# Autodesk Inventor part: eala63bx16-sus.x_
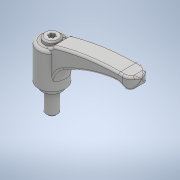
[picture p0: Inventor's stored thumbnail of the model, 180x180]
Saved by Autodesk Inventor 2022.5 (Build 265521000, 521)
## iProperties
Created: 2018-05
Part Number: eala63bx16-sus.x_
Material: 一般
Document SubType Name: Modeling
Designer: imaocorp
Density: 1 g/cm^3
Appearance: 既定
Sending System: SOLIDWORKS 2016-2016286
MC: AMD64
MC_MODEL: AMD64 Family 21 Model 2 Stepping 0, AuthenticAMD
OS: Windows_NT
FRU: Parasolid Version 28.0, build 224,  7-29-2016
FORMAT: text
GUISE: transmit
KEY: eala63bx16-sus
FILE: eala63bx16-sus.x_t
DATE: Fri May 18 11:30:19 2018
Author: imaocorp
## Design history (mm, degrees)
feature "Base1"
node "ソリッド1"
